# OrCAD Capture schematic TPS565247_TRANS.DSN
size C; title: TPS565247, 3-V to 16-V input, 5-A Synchronous; rev: 1.0; note: Datasheet: SLUSEN1     EVM: SLUUCJ3A; note: Synchronous Step Down Converter; note: Step-Down Voltage Regulator
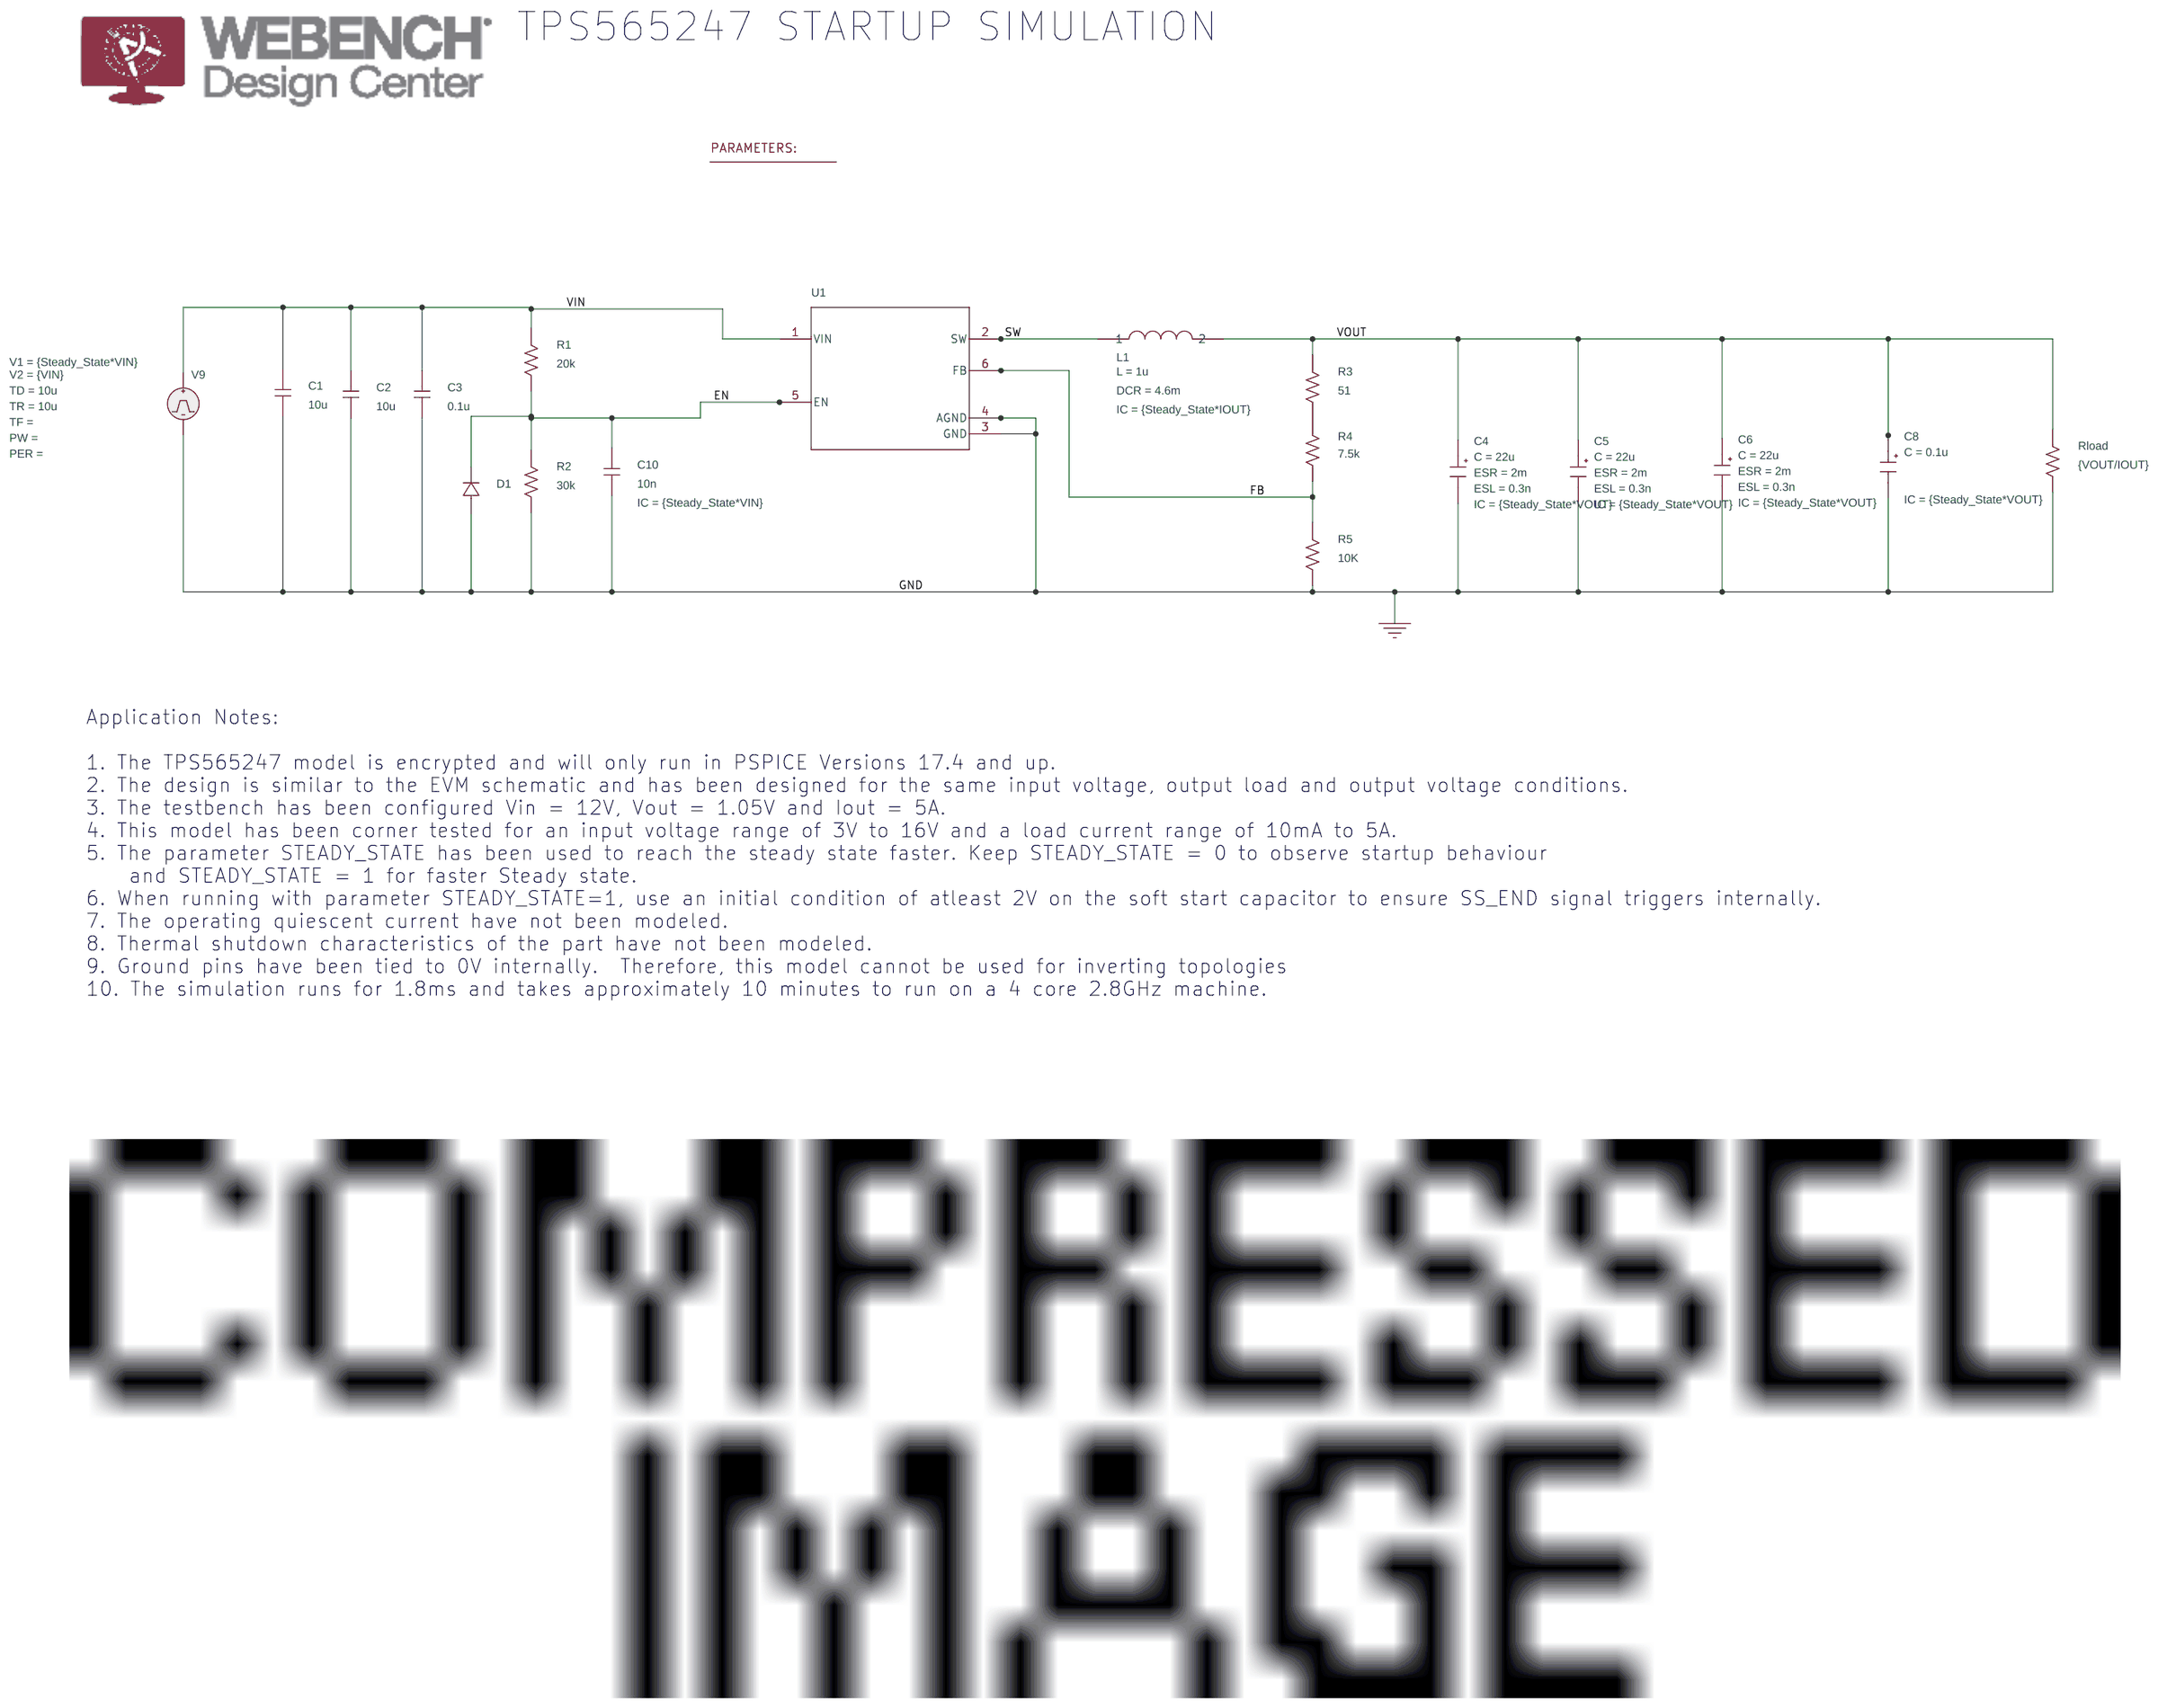
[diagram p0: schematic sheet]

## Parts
3  PARAM
C1  10u  [RAD/CK05]
C2  10u  [RAD/CK05]
C3  0.1u  [RAD/CK05]
C4  CESR
C5  CESR
C6  CESR
C8  CESR
C10  10n  [RAD/CK05]
D1  Dbreak
L1  LDCR
R1  20k  [AX/RC05]
R2  30k  [AX/RC05]
R3  51  [AX/RC05]
R4  7.5k  [AX/RC05]
R5  10K  [AX/RC05]
Rload  {VOUT/IOUT}  [AX/RC05]
U1  Value  [DRL0006A-MFG]
V9  VPULSE

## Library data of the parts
3 = PARAM: IOUT: 5; Steady_State: 0; VIN: 12; VOUT: 1.05
C1-C3 = C
C4-C6 = CESR_0: C: 22u; ESL: 0.3n; ESR: 2m; IC: {Steady_State*VOUT}
C8 = CESR_0: C: 0.1u; ESL: 0.3n; ESR: 1m; IC: {Steady_State*VOUT}
C10 = C: IC: {Steady_State*VIN}
D1 = Dbreak
L1 = LDCR: DCR: 4.6m; IC: {Steady_State*IOUT}; L: 1u
R1-R5 Rload = R
U1 = TPS565247DRL_TRANS
V9 = VPULSE: TD: 10u; TR: 10u; V1: {Steady_State*VIN}; V2: {VIN}

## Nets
VIN: C1.1 C2.1 C3.1 R1.1 U1.1(VIN) V9.1(+)
0: C1.2 C2.2 C3.2 C4.2(OUT) C5.2(OUT) C6.2(OUT) C8.2(OUT) C10.2 D1.0(1) R2.2 R5.2 Rload.2 U1.3(GND) U1.4(AGND) V9.2(-)
EN: C10.1 D1.1(2) R1.2 R2.1 U1.5(EN)
FB: R4.2 R5.1 U1.6(FB)
SW: L1.1 U1.2(SW)
VOUT: C4.1(IN) C5.1(IN) C6.1(IN) C8.1(IN) L1.2 R3.1 Rload.1
N16780365: R3.2 R4.1

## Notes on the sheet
- TPS565247 STARTUP SIMULATION
- Application Notes:
  1. The TPS565247 model is encrypted and will only run in PSPICE Versions 17.4 and up.
  2. The design is similar to the EVM schematic and has been designed for the same input voltage, output load and output voltage conditions.
  3. The testbench has been configured Vin = 12V, Vout = 1.05V and Iout = 5A.
  4. This model has been corner tested for an input voltage range of 3V to 16V and a load current range of 10mA to 5A.
  5. The parameter STEADY_STATE has been used to reach the steady state faster. Keep STEADY_STATE = 0 to observe startup behaviour
      and STEADY_STATE = 1 for faster Steady state.
  6. When running with parameter STEADY_STATE=1, use an initial condition of atleast 2V on the soft start capacitor to ensure SS_END signal triggers internally.
  7. The operating quiescent current have not been modeled.
  8. Thermal shutdown characteristics of the part have not been modeled.
  9. Ground pins have been tied to 0V internally.  Therefore, this model cannot be used for inverting topologies
  10. The simulation runs for 1.8ms and takes approximately 10 minutes to run on a 4 core 2.8GHz machine.
